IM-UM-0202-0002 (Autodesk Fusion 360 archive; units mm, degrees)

design "IM-UM-0202-0002" references "SFP SLOT", "LED", "Digitus_DN-651107_LAN-Switch 19.5mm", "3M Screw", "POWER", "ethernet 2 ports"
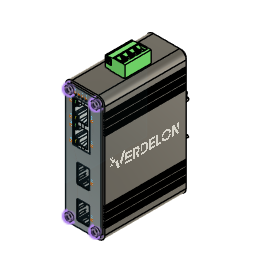
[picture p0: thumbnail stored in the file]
sketch "Sketch1" plane through (0, 0, 0) normal (0, 1, 0) x axis (1, 0, 0)
  line L1 (25, 0) -> (5, 0)
  line L2 (30, -90) -> (30, -5)
  line L3 (5, -95) -> (25, -95)
  line L4 (0, -5) -> (0, -90)
  arc A1 centre (5, -90) radius 5 clockwise from (5, -95) to (0, -90)
  arc A2 centre (25, -90) radius 5 clockwise from (30, -90) to (25, -95)
  arc A3 centre (5, -5) radius 5 clockwise from (0, -5) to (5, 0)
  arc A4 centre (25, -5) radius 5 clockwise from (25, 0) to (30, -5)
  point P1 (0, 0)
  point P2 (0, 0)
  point P4 (0, -95)
  point P3 (30, 0)
  horizontal L1
  vertical L2
  horizontal L3
  vertical L4
  coincident P1 P2
  coincident P4 L3
  coincident P4 L4
  tangent L3 A1
  tangent L4 A1
  tangent L2 A2
  tangent L3 A2
  equal A1 A2
  coincident P2 L1
  coincident P2 L4
  tangent L1 A3
  tangent L4 A3
  equal A1 A3
  coincident P3 L1
  coincident P3 L2
  tangent L1 A4
  tangent L2 A4
  equal A1 A4
  dimension "d1" distance P2 P4 = 95
  dimension "d2" distance P2 P3 = 30
  dimension "d3" radius A1 = 5
extrude "Extrude1" new body sketch "Sketch1" along normal blind 65
sketch "Sketch2" plane through (0, 0, 0) normal (0, -1, 0) x axis (1, 0, 0)
  line L1 (5, 95) -> (25, 95)
  line L2 (0, 5) -> (0, 90)
  line L3 (25, 0) -> (5, 0)
  line L4 (30, 90) -> (30, 5)
  line L5 (1.5, 5) -> (1.5, 90)
  line L6 (25, 1.5) -> (5, 1.5)
  line L7 (28.5, 90) -> (28.5, 5)
  line L8 (5, 93.5) -> (25, 93.5)
  line L9 (0, 5) -> (0, 90)
  line L10 (25, 0) -> (5, 0)
  line L11 (30, 90) -> (30, 5)
  line L12 (5, 95) -> (25, 95)
  arc A1 centre (25, 90) radius 5 clockwise from (25, 95) to (30, 90)
  arc A2 centre (5, 90) radius 5 clockwise from (0, 90) to (5, 95)
  arc A3 centre (5, 5) radius 5 clockwise from (5, 0) to (0, 5)
  arc A4 centre (25, 5) radius 5 clockwise from (30, 5) to (25, 0)
  arc A5 centre (5, 5) radius 3.5 clockwise from (5, 1.5) to (1.5, 5)
  arc A6 centre (25, 5) radius 3.5 clockwise from (28.5, 5) to (25, 1.5)
  arc A7 centre (25, 90) radius 3.5 clockwise from (25, 93.5) to (28.5, 90)
  arc A8 centre (5, 90) radius 3.5 clockwise from (1.5, 90) to (5, 93.5)
  arc A9 centre (5, 5) radius 5 clockwise from (5, 0) to (0, 5)
  arc A10 centre (25, 5) radius 5 clockwise from (30, 5) to (25, 0)
  arc A11 centre (25, 90) radius 5 clockwise from (25, 95) to (30, 90)
  arc A12 centre (5, 90) radius 5 clockwise from (0, 90) to (5, 95)
  dimension "d6" = -1.5
  dimension "d7" distance L2 = 0
extrude "Extrude2" cut sketch "Sketch2" against normal blind 1.5
sketch "Sketch3" plane through (0, 65, 0) normal (0, 1, 0) x axis (-1, 0, 0)
  line L1 (-30, 5) -> (-30, 90)
  line L2 (-5, 0) -> (-25, 0)
  line L3 (0, 90) -> (0, 5)
  line L4 (-25, 95) -> (-5, 95)
  line L5 (-28.5, 5) -> (-28.5, 90)
  line L6 (-5, 1.5) -> (-25, 1.5)
  line L7 (-1.5, 90) -> (-1.5, 5)
  line L8 (-25, 93.5) -> (-5, 93.5)
  line L9 (-30, 5) -> (-30, 90)
  line L10 (-5, 0) -> (-25, 0)
  line L11 (0, 90) -> (0, 5)
  line L12 (-25, 95) -> (-5, 95)
  arc A1 centre (-25, 90) radius 5 clockwise from (-30, 90) to (-25, 95)
  arc A2 centre (-25, 5) radius 5 clockwise from (-25, 0) to (-30, 5)
  arc A3 centre (-5, 5) radius 5 clockwise from (0, 5) to (-5, 0)
  arc A4 centre (-5, 90) radius 5 clockwise from (-5, 95) to (0, 90)
  arc A5 centre (-25, 5) radius 3.5 clockwise from (-25, 1.5) to (-28.5, 5)
  arc A6 centre (-5, 5) radius 3.5 clockwise from (-1.5, 5) to (-5, 1.5)
  arc A7 centre (-5, 90) radius 3.5 clockwise from (-5, 93.5) to (-1.5, 90)
  arc A8 centre (-25, 90) radius 3.5 clockwise from (-28.5, 90) to (-25, 93.5)
  arc A9 centre (-25, 5) radius 5 clockwise from (-25, 0) to (-30, 5)
  arc A10 centre (-5, 5) radius 5 clockwise from (0, 5) to (-5, 0)
  arc A11 centre (-5, 90) radius 5 clockwise from (-5, 95) to (0, 90)
  arc A12 centre (-25, 90) radius 5 clockwise from (-30, 90) to (-25, 95)
  dimension "d10" = -1.5
  dimension "d11" distance L1 = 0
extrude "Extrude3" cut sketch "Sketch3" against normal blind 1.5
sketch "Sketch4" plane through (0, 1.5, 0) normal (0, -1, 0) x axis (1, 0, 0)
  line L1 (25, 93.5) -> (5, 93.5)
  line L2 (28.5, 5) -> (28.5, 90)
  line L3 (5, 1.5) -> (25, 1.5)
  line L4 (1.5, 90) -> (1.5, 5)
  line L5 (0, 5) -> (0, 90)
  line L6 (25, 0) -> (5, 0)
  line L7 (30, 90) -> (30, 5)
  line L8 (5, 95) -> (25, 95)
  line L9 (-15.934, 47.5) -> (1.5, 47.5)
  line L10 (15, 105) -> (15, 93.5)
  line L11 (0.5, 85.5) -> (0, 85.5)
  line L12 (0.5, 84.5) -> (0.5, 85.5)
  line L13 (0, 84.5) -> (0.5, 84.5)
  line L14 (0, 85.5) -> (0, 84.5)
  line L15 (0, 84) -> (0, 83)
  line L16 (0, 83) -> (0.5, 83)
  line L17 (0.5, 84) -> (0, 84)
  line L18 (0.5, 83) -> (0.5, 84)
  line L19 (0, 82.5) -> (0, 81.5)
  line L20 (0, 81.5) -> (0.5, 81.5)
  line L21 (0.5, 82.5) -> (0, 82.5)
  line L22 (0.5, 81.5) -> (0.5, 82.5)
  line L23 (0, 79) -> (0.5, 79)
  line L24 (0, 77) -> (0, 76)
  line L25 (0, 78.5) -> (0, 77.5)
  line L26 (0.5, 78.5) -> (0, 78.5)
  line L27 (0.5, 80) -> (0, 80)
  line L28 (0, 76) -> (0.5, 76)
  line L29 (0.5, 76) -> (0.5, 77)
  line L30 (0, 80) -> (0, 79)
  line L31 (0.5, 77) -> (0, 77)
  line L32 (0, 77.5) -> (0.5, 77.5)
  line L33 (0.5, 77.5) -> (0.5, 78.5)
  line L34 (0.5, 79) -> (0.5, 80)
  line L35 (0, 73.5) -> (0.5, 73.5)
  line L36 (0, 71.5) -> (0, 70.5)
  line L37 (0, 73) -> (0, 72)
  line L38 (0.5, 73) -> (0, 73)
  line L39 (0.5, 74.5) -> (0, 74.5)
  line L40 (0, 70.5) -> (0.5, 70.5)
  line L41 (0.5, 70.5) -> (0.5, 71.5)
  line L42 (0, 74.5) -> (0, 73.5)
  line L43 (0.5, 71.5) -> (0, 71.5)
  line L44 (0, 72) -> (0.5, 72)
  line L45 (0.5, 72) -> (0.5, 73)
  line L46 (0.5, 73.5) -> (0.5, 74.5)
  line L47 (0, 23.5) -> (0, 24.5)
  line L48 (0.5, 17.5) -> (0.5, 16.5)
  line L49 (0.5, 19) -> (0.5, 18)
  line L50 (0, 20.5) -> (0, 21.5)
  line L51 (0, 16) -> (0.5, 16)
  line L52 (0.5, 11) -> (0, 11)
  line L53 (0.5, 12) -> (0.5, 11)
  line L54 (0, 12) -> (0.5, 12)
  line L55 (0.5, 15) -> (0, 15)
  line L56 (0, 15) -> (0, 16)
  line L57 (0, 17.5) -> (0.5, 17.5)
  line L58 (0, 19) -> (0.5, 19)
  line L59 (0.5, 16) -> (0.5, 15)
  line L60 (0, 11) -> (0, 12)
  line L61 (0, 22) -> (0, 23)
  line L62 (0.5, 18) -> (0, 18)
  line L63 (0, 13.5) -> (0.5, 13.5)
  line L64 (0.5, 23) -> (0.5, 22)
  line L65 (0.5, 10.5) -> (0.5, 9.5)
  line L66 (0, 10.5) -> (0.5, 10.5)
  line L67 (0.5, 23.5) -> (0, 23.5)
  line L68 (0.5, 12.5) -> (0, 12.5)
  line L69 (0.5, 21.5) -> (0.5, 20.5)
  line L70 (0.5, 16.5) -> (0, 16.5)
  line L71 (0, 12.5) -> (0, 13.5)
  line L72 (0, 16.5) -> (0, 17.5)
  line L73 (0, 24.5) -> (0.5, 24.5)
  line L74 (0.5, 24.5) -> (0.5, 23.5)
  line L75 (0, 21.5) -> (0.5, 21.5)
  line L76 (0.5, 9.5) -> (0, 9.5)
  line L77 (0.5, 13.5) -> (0.5, 12.5)
  line L78 (0, 9.5) -> (0, 10.5)
  line L79 (0, 18) -> (0, 19)
  line L80 (0.5, 22) -> (0, 22)
  line L81 (0.5, 20.5) -> (0, 20.5)
  line L82 (0, 23) -> (0.5, 23)
  line L83 (30, 76) -> (29.5, 76)
  line L84 (30, 70.5) -> (29.5, 70.5)
  line L85 (29.5, 73.5) -> (29.5, 74.5)
  line L86 (30, 84.5) -> (29.5, 84.5)
  line L87 (30, 73) -> (30, 72)
  line L88 (30, 83) -> (29.5, 83)
  line L89 (30, 72) -> (29.5, 72)
  line L90 (30, 73.5) -> (29.5, 73.5)
  line L91 (29.5, 83) -> (29.5, 84)
  line L92 (29.5, 77) -> (30, 77)
  line L93 (30, 71.5) -> (30, 70.5)
  line L94 (30, 78.5) -> (30, 77.5)
  line L95 (29.5, 73) -> (30, 73)
  line L96 (29.5, 82.5) -> (30, 82.5)
  line L97 (30, 81.5) -> (29.5, 81.5)
  line L98 (29.5, 84) -> (30, 84)
  line L99 (29.5, 77.5) -> (29.5, 78.5)
  line L100 (30, 79) -> (29.5, 79)
  line L101 (29.5, 84.5) -> (29.5, 85.5)
  line L102 (30, 77) -> (30, 76)
  line L103 (30, 74.5) -> (30, 73.5)
  line L104 (29.5, 79) -> (29.5, 80)
  line L105 (29.5, 81.5) -> (29.5, 82.5)
  line L106 (30, 80) -> (30, 79)
  line L107 (29.5, 85.5) -> (30, 85.5)
  line L108 (30, 85.5) -> (30, 84.5)
  line L109 (29.5, 76) -> (29.5, 77)
  line L110 (30, 84) -> (30, 83)
  line L111 (29.5, 71.5) -> (30, 71.5)
  line L112 (29.5, 78.5) -> (30, 78.5)
  line L113 (29.5, 70.5) -> (29.5, 71.5)
  line L114 (30, 82.5) -> (30, 81.5)
  line L115 (29.5, 80) -> (30, 80)
  line L116 (29.5, 74.5) -> (30, 74.5)
  line L117 (30, 77.5) -> (29.5, 77.5)
  line L118 (29.5, 72) -> (29.5, 73)
  line L119 (30, 17.5) -> (29.5, 17.5)
  line L120 (29.5, 23.5) -> (30, 23.5)
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  point P22 (1.5, 47.5)
  point P24 (15, 93.5)
  point P26 (0, 85.5)
  point P81 (0, 9.5)
  point P27 (0.5, 85.5)
  point P73 (0.5, 9.5)
  point P28 (0.5, 84.5)
  point P67 (0.5, 10.5)
  point P29 (0, 84.5)
  point P89 (0, 10.5)
  point P30 (0, 83)
  point P91 (0, 12)
  point P31 (0, 84)
  point P86 (0, 11)
  point P32 (0.5, 83)
  point P65 (0.5, 12)
  point P33 (0.5, 84)
  point P77 (0.5, 11)
  point P34 (0, 81.5)
  point P70 (0, 13.5)
  point P35 (0, 82.5)
  point P68 (0, 12.5)
  point P36 (0.5, 81.5)
  point P80 (0.5, 13.5)
  point P37 (0.5, 82.5)
  point P82 (0.5, 12.5)
  point P38 (0, 79)
  point P83 (0, 16)
  point P39 (0.5, 79)
  point P76 (0.5, 16)
  point P40 (0.5, 80)
  point P74 (0.5, 15)
  point P41 (0, 76)
  point P71 (0, 19)
  point P42 (0, 77)
  point P62 (0, 18)
  point P43 (0.5, 77)
  point P63 (0.5, 18)
  point P44 (0, 77.5)
  point P93 (0, 17.5)
  point P45 (0, 78.5)
  point P92 (0, 16.5)
  point P46 (0.5, 78.5)
  point P90 (0.5, 16.5)
  point P47 (0, 80)
  point P96 (0, 15)
  point P48 (0.5, 76)
  point P95 (0.5, 19)
  point P49 (0.5, 77.5)
  point P97 (0.5, 17.5)
  point P50 (0, 73.5)
  point P87 (0, 21.5)
  point P51 (0.5, 73.5)
  point P88 (0.5, 21.5)
  point P52 (0.5, 74.5)
  point P94 (0.5, 20.5)
  point P53 (0, 70.5)
  point P66 (0, 24.5)
  point P54 (0, 71.5)
  point P64 (0, 23.5)
  point P55 (0.5, 71.5)
  point P78 (0.5, 23.5)
  point P56 (0, 72)
  point P72 (0, 23)
  point P57 (0, 73)
  point P75 (0, 22)
  point P58 (0.5, 73)
  point P69 (0.5, 22)
  point P59 (0, 74.5)
  point P79 (0, 20.5)
  point P60 (0.5, 70.5)
  point P84 (0.5, 24.5)
  point P61 (0.5, 72)
  point P85 (0.5, 23)
  point P106 (30, 85.5)
  point P121 (29.5, 85.5)
  point P122 (29.5, 84.5)
  point P118 (30, 84.5)
  point P120 (30, 83)
  point P119 (30, 84)
  point P123 (29.5, 83)
  point P126 (29.5, 84)
  point P125 (30, 81.5)
  point P124 (30, 82.5)
  point P100 (29.5, 81.5)
  point P98 (29.5, 82.5)
  point P102 (30, 79)
  point P99 (29.5, 79)
  point P101 (29.5, 80)
  point P131 (30, 76)
  point P129 (30, 77)
  point P127 (29.5, 77)
  point P130 (30, 77.5)
  point P133 (30, 78.5)
  point P128 (29.5, 78.5)
  point P132 (30, 80)
  point P113 (29.5, 76)
  point P116 (29.5, 77.5)
  point P112 (30, 73.5)
  point P117 (29.5, 73.5)
  point P115 (29.5, 74.5)
  point P114 (30, 70.5)
  point P111 (30, 71.5)
  point P105 (29.5, 71.5)
  point P108 (30, 72)
  point P104 (30, 73)
  point P103 (29.5, 73)
  point P109 (30, 74.5)
  point P110 (29.5, 70.5)
  point P107 (29.5, 72)
  point P169 (30, 18)
  point P134 (29.5, 18)
  point P138 (30, 23.5)
  point P166 (29.5, 12)
  point P139 (30, 24.5)
  point P160 (29.5, 10.5)
  point P140 (30, 12.5)
  point P135 (29.5, 22)
  point P147 (30, 13.5)
  point P136 (30, 19)
  point P155 (30, 23)
  point P148 (29.5, 9.5)
  point P162 (29.5, 15)
  point P168 (30, 22)
  point P157 (29.5, 16)
  point P141 (29.5, 11)
  point P165 (29.5, 23.5)
  point P167 (30, 20.5)
  point P151 (29.5, 13.5)
  point P143 (30, 9.5)
  point P152 (29.5, 12.5)
  point P150 (30, 16)
  point P145 (29.5, 24.5)
  point P142 (29.5, 23)
  point P164 (30, 11)
  point P149 (30, 21.5)
  point P146 (29.5, 21.5)
  point P154 (30, 10.5)
  point P144 (29.5, 16.5)
  point P153 (30, 12)
  point P158 (30, 16.5)
  point P156 (30, 17.5)
  point P163 (29.5, 20.5)
  point P161 (29.5, 19)
  point P159 (30, 15)
  point P137 (29.5, 17.5)
  midpoint L4 P22
  perpendicular L4 L9
  midpoint L1 P24
  perpendicular L8 L10
  horizontal L11
  vertical L12
  horizontal L13
  vertical L14
  coincident L5 P26
  symmetric L9 P26 P81
  symmetric L9 P27 P73
  symmetric L9 P28 P67
  symmetric L9 P29 P89
  symmetric L9 P30 P91
  symmetric L9 P31 P86
  symmetric L9 P32 P65
  symmetric L9 P33 P77
  symmetric L9 P34 P70
  symmetric L9 P35 P68
  symmetric L9 P36 P80
  symmetric L9 P37 P82
  symmetric L9 P38 P83
  symmetric L9 P39 P76
  symmetric L9 P40 P74
  symmetric L9 P41 P71
  symmetric L9 P42 P62
  symmetric L9 P43 P63
  symmetric L9 P44 P93
  symmetric L9 P45 P92
  symmetric L9 P46 P90
  symmetric L9 P47 P96
  symmetric L9 P48 P95
  symmetric L9 P49 P97
  symmetric L9 P50 P87
  symmetric L9 P51 P88
  symmetric L9 P52 P94
  symmetric L9 P53 P66
  symmetric L9 P54 P64
  symmetric L9 P55 P78
  symmetric L9 P56 P72
  symmetric L9 P57 P75
  symmetric L9 P58 P69
  symmetric L9 P59 P79
  symmetric L9 P60 P84
  symmetric L9 P61 P85
  symmetric L10 P26 P106
  symmetric L10 P27 P121
  symmetric L10 P28 P122
  symmetric L10 P29 P118
  symmetric L10 P30 P120
  symmetric L10 P31 P119
  symmetric L10 P32 P123
  symmetric L10 P33 P126
  symmetric L10 P34 P125
  symmetric L10 P35 P124
  symmetric L10 P36 P100
  symmetric L10 P37 P98
  symmetric L10 P38 P102
  symmetric L10 P39 P99
  symmetric L10 P40 P101
  symmetric L10 P41 P131
  symmetric L10 P42 P129
  symmetric L10 P43 P127
  symmetric L10 P44 P130
  symmetric L10 P45 P133
  symmetric L10 P46 P128
  symmetric L10 P47 P132
  symmetric L10 P48 P113
  symmetric L10 P49 P116
  symmetric L10 P50 P112
  symmetric L10 P51 P117
  symmetric L10 P52 P115
  symmetric L10 P53 P114
  symmetric L10 P54 P111
  symmetric L10 P55 P105
  symmetric L10 P56 P108
  symmetric L10 P57 P104
  symmetric L10 P58 P103
  symmetric L10 P59 P109
  symmetric L10 P60 P110
  symmetric L10 P61 P107
  symmetric L10 P62 P169
  symmetric L10 P63 P134
  symmetric L10 P64 P138
  symmetric L10 P65 P166
  symmetric L10 P66 P139
  symmetric L10 P67 P160
  symmetric L10 P68 P140
  symmetric L10 P69 P135
  symmetric L10 P70 P147
  symmetric L10 P71 P136
  symmetric L10 P72 P155
  symmetric L10 P73 P148
  symmetric L10 P74 P162
  symmetric L10 P75 P168
  symmetric L10 P76 P157
  symmetric L10 P77 P141
  symmetric L10 P78 P165
  symmetric L10 P79 P167
  symmetric L10 P80 P151
  symmetric L10 P81 P143
  symmetric L10 P82 P152
  symmetric L10 P83 P150
  symmetric L10 P84 P145
  symmetric L10 P85 P142
  symmetric L10 P86 P164
  symmetric L10 P87 P149
  symmetric L10 P88 P146
  symmetric L10 P89 P154
  symmetric L10 P90 P144
  symmetric L10 P91 P153
  symmetric L10 P92 P158
  symmetric L10 P93 P156
  symmetric L10 P94 P163
  symmetric L10 P95 P161
  symmetric L10 P96 P159
  symmetric L10 P97 P137
  dimension "d14" distance P26 P29 = 1
  dimension "d15" distance P26 P27 = 0.5
  dimension "d24" distance L9 L40 = 23
  dimension "d18" R-Pattern1-uDistance = 0
  dimension "d19" R-Pattern1-vDistance = -3
  dimension "d22" R-Pattern2-uDistance = 0
  dimension "d23" R-Pattern2-vDistance = -11
extrude "Extrude4" cut sketch "Sketch4" against normal blind 64
sketch "Sketch5" plane through (0, 0, 0) normal (0, -1, 0) x axis (1, 0, 0)
  line L1 (5, 93.5) -> (25, 93.5)
  line L2 (1.5, 5) -> (1.5, 90)
  line L3 (25, 1.5) -> (5, 1.5)
  line L4 (28.5, 90) -> (28.5, 5)
  line L5 (15, 47.5) -> (15, 93.5)
  line L6 (15, 47.5) -> (1.5, 47.5)
  line L7 (19.096, 6.0033) -> (10.904, 6.0033)
  line L8 (19.85, 19.7493) -> (19.85, 6.7573)
  line L9 (10.904, 20.5033) -> (19.096, 20.5033)
  line L10 (10.15, 6.7573) -> (10.15, 19.7493)
  line L11 (19.096, 30.0033) -> (10.904, 30.0033)
  line L12 (19.85, 43.7493) -> (19.85, 30.7573)
  line L13 (10.904, 44.5033) -> (19.096, 44.5033)
  line L14 (10.15, 30.7573) -> (10.15, 43.7493)
  line L15 (20.16, 86.4) -> (7, 86.4)
  line L16 (20.16, 54.5) -> (20.16, 86.4)
  line L17 (7, 54.5) -> (20.16, 54.5)
  line L18 (7, 86.4) -> (7, 54.5)
  line L19 (5, 6) -> (5, 1.5)
  line L20 (5, 6) -> (1.5, 6)
  arc A1 centre (5, 90) radius 3.5 clockwise from (1.5, 90) to (5, 93.5)
  arc A2 centre (5, 5) radius 3.5 clockwise from (5, 1.5) to (1.5, 5)
  arc A3 centre (25, 5) radius 3.5 clockwise from (28.5, 5) to (25, 1.5)
  arc A4 centre (25, 90) radius 3.5 clockwise from (25, 93.5) to (28.5, 90)
  circle C1 centre (9.25, 88.4) radius 0.75
  circle C2 centre (11.9167, 88.4) radius 0.75
  circle C3 centre (14.5833, 88.4) radius 0.75
  circle C4 centre (17.25, 88.4) radius 0.75
  arc A5 centre (10.904, 6.7573) radius 0.754 clockwise from (10.904, 6.0033) to (10.15, 6.7573)
  arc A6 centre (19.096, 6.7573) radius 0.754 clockwise from (19.85, 6.7573) to (19.096, 6.0033)
  arc A7 centre (19.096, 19.7493) radius 0.754 clockwise from (19.096, 20.5033) to (19.85, 19.7493)
  arc A8 centre (10.904, 19.7493) radius 0.754 clockwise from (10.15, 19.7493) to (10.904, 20.5033)
  arc A9 centre (10.904, 30.7573) radius 0.754 clockwise from (10.904, 30.0033) to (10.15, 30.7573)
  arc A10 centre (19.096, 30.7573) radius 0.754 clockwise from (19.85, 30.7573) to (19.096, 30.0033)
  arc A11 centre (19.096, 43.7493) radius 0.754 clockwise from (19.096, 44.5033) to (19.85, 43.7493)
  arc A12 centre (10.904, 43.7493) radius 0.754 clockwise from (10.15, 43.7493) to (10.904, 44.5033)
  circle C5 centre (5, 6) radius 1.5
  circle C6 centre (25, 6) radius 1.5
  circle C7 centre (5, 90) radius 1.5
  circle C8 centre (25, 90) radius 1.5
  point P14 (15, 93.5)
  point P15 (1.5, 47.5)
  point P17 (10.15, 6.0033)
  point P18 (19.85, 20.5033)
  point P19 (10.15, 20.5033)
  point P7 (5, 1.5)
  point P52 (5, 1.5)
  point P53 (1.5, 6)
  point P54 (5, 6)
  point P55 (5, 6)
  point P20 (7, 86.4)
  point P23 (7, 54.5)
  point P21 (20.16, 86.4)
  point P24 (9.25, 88.4)
  midpoint L1 P14
  perpendicular L1 L5
  midpoint L2 P15
  perpendicular L2 L6
  horizontal L7
  vertical L8
  horizontal L9
  vertical L10
  symmetric L5 L8 L10
  horizontal L15
  vertical L16
  horizontal L17
  vertical L18
  coincident P17 L7
  coincident P17 L10
  tangent L7 A5
  tangent L10 A5
  tangent L7 A6
  tangent L8 A6
  equal A5 A6
  coincident P18 L8
  coincident P18 L9
  tangent L8 A7
  tangent L9 A7
  equal A5 A7
  coincident P19 L9
  coincident P19 L10
  tangent L9 A8
  tangent L10 A8
  equal A5 A8
  tangent L11 A9
  tangent L14 A9
  equal A5 A9
  tangent L11 A10
  tangent L12 A10
  equal A5 A10
  tangent L12 A11
  tangent L13 A11
  equal A5 A11
  tangent L13 A12
  tangent L14 A12
  equal A5 A12
  coincident P7 P52
  perpendicular L3 L19
  coincident L2 P53
  perpendicular L19 L20
  coincident P54 P55
  dimension "d27" distance P17 P19 = 14.5
  dimension "d28" distance P18 P19 = 9.7
  dimension "d33" distance P20 P23 = 31.9
  dimension "d34" distance P20 P21 = 13.16
  dimension "d35" distance L5 L18 = 8
  dimension "d36" distance L6 L17 = 7
  dimension "d37" distance L6 L13 = 2.9967
  dimension "d38" diameter C1 = 1.5
  dimension "d39" distance L15 P24 = 2
  dimension "d44" distance L18 P24 = 2.25
  dimension "d65" radius A5 = 0.754
  dimension "d42" R-Pattern2-uDistance = 8
  dimension "d43" R-Pattern2-vDistance = 0
  dimension "d81" R-Pattern2-uDistance = 20
  dimension "d82" R-Pattern2-vDistance = 0
  dimension "d85" R-Pattern3-uDistance = 0
  dimension "d86" R-Pattern3-vDistance = 84
extrude "Extrude5" cut sketch "Sketch5" profile of L5 L7 L8 L9 L10 L11 L12 L13 L14 L15 L16 L17 L18 C1 C2 C3 C4 A5 A6 A7 A8 A9 A10 A11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 against normal blind 2
shell "Shell1" innerThickness 1
sketch "Sketch6" plane through (0, 0, 95) normal (0, 0, 1) x axis (-1, 0, 0)
  line L1 (-5, -63.5) -> (-25, -63.5)
  line L2 (-5, -1.5) -> (-5, -63.5)
  line L3 (-25, -1.5) -> (-5, -1.5)
  line L4 (-25, -63.5) -> (-25, -1.5)
  line L5 (-15, -32.5) -> (-15, -63.5)
  line L6 (-15, -32.5) -> (-5, -32.5)
  line L7 (-23.17, -42.5) -> (-15.5, -42.5)
  line L8 (-23.17, -22.5) -> (-23.17, -42.5)
  line L9 (-15.5, -22.5) -> (-23.17, -22.5)
  line L10 (-15.5, -42.5) -> (-15.5, -22.5)
  point P6 (-15, -63.5)
  point P7 (-5, -32.5)
  point P10 (-23.17, -42.5)
  point P11 (-23.17, -22.5)
  point P9 (-15.5, -42.5)
  midpoint L1 P6
  perpendicular L1 L5
  midpoint L2 P7
  perpendicular L5 L6
  horizontal L7
  vertical L8
  horizontal L9
  vertical L10
  symmetric L6 L7 L9
  dimension "d48" distance P10 P11 = 20
  dimension "d49" distance P9 P10 = 7.67
  dimension "d50" distance L5 L10 = 0.5
extrude "Extrude6" cut sketch "Sketch6" profile of L7 L8 L9 L10 against normal blind 5
component_insert "Component Insert3"
joint "Assemble1" alignAngle 0 alignOffsetX 0 alignOffsetY 0 alignOffsetZ 2.25
rectangular_pattern "00000000-0000-0000-0000-000000000000" uSpaceDistance 8 vSpaceDistance 0
component_insert "Component Insert4"
position "Position1"
rectangular_pattern "00000000-0000-0000-0000-000000000000" uSpaceDistance -24 vSpaceDistance 0
component_insert "Component Insert6"
component_insert "Component Insert7"
component_insert "Component Insert10"
position "Position2"
sketch "Sketch8" plane through (0, 0, 0) normal (0, -1, 0) x axis (1, 0, 0)
  dimension "d66" = 1.5
  dimension "d67" = 1.5
  dimension "d68" = 1.5
  dimension "d69" = 1.5
  dimension "d70" = 1.5
  dimension "d71" = 1.5
  dimension "d72" = 1.5
  dimension "d73" = 1.5
  dimension "d74" = 1
  dimension "d75" = 1
  dimension "d77" = 1
  dimension "d78" = 1
component_insert "Component Insert14"
joint "Assemble2" alignAngle 90 alignOffsetX 0 alignOffsetY 0 alignOffsetZ -6
rectangular_pattern "00000000-0000-0000-0000-000000000000" uSpaceDistance 20 vSpaceDistance 0
rectangular_pattern "00000000-0000-0000-0000-000000000000" uSpaceDistance -84 vSpaceDistance 0
sketch "Sketch9" plane through (0, 0, 0) normal (-1, 0, 0) x axis (0, -1, 0)
  line L1 (-1.5, 24.5) -> (-63.5, 24.5)
  line L2 (-1.5, 70.5) -> (-1.5, 24.5)
  line L3 (-63.5, 70.5) -> (-1.5, 70.5)
  line L4 (-63.5, 24.5) -> (-63.5, 70.5)
decal "Decal1"
decal "Decal2"
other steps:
joint_origin "JointOrigin1"
joint_origin "JointOrigin2" sketch "Sketch8"

design "POWER"
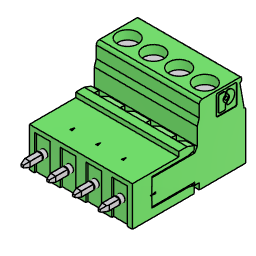
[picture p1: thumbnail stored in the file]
description: STEP AP214
part number: POWER

design "ethernet 2 ports"
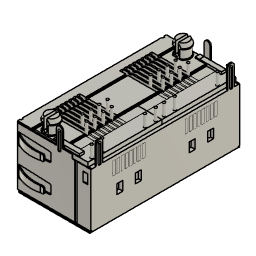
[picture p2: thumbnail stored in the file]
description: STEP AP214
part number: ethernet 2 ports

design "3M Screw"
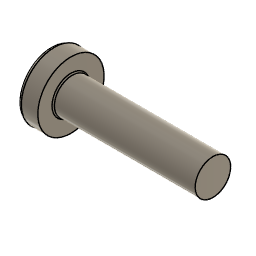
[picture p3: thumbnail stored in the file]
description: STEP AP214
part number: 3M Screw

design "Digitus_DN-651107_LAN-Switch 19.5mm"
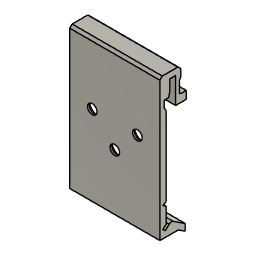
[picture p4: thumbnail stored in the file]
description: STEP AP214
part number: Digitus_DN-651107_LAN-Switch 19.5mm

design "LED"
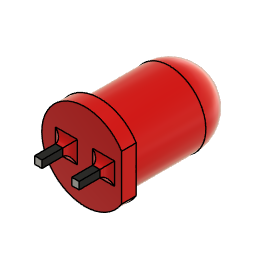
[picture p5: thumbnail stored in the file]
description: STEP AP214
part number: LED

design "SFP SLOT"
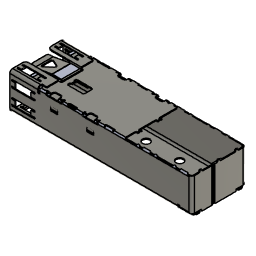
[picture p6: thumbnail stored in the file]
description: STEP AP214
part number: SFP SLOT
